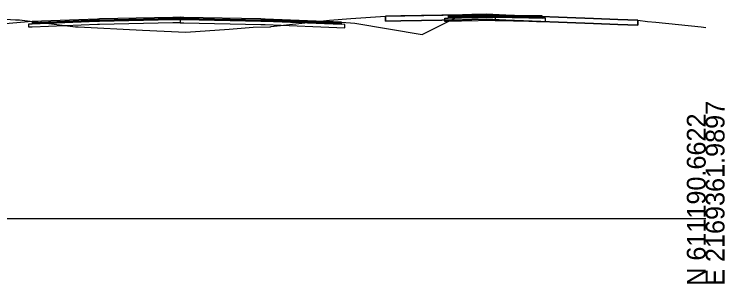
# Model space of a CAD drawing. Extents: x -26 to 1303, y -3010 to 12038.
# Drawn here: x 1197.1 to 1302.8, y 5990.3 to 6030.4 of the extents above; entities that cross this region are included whole.
import ezdxf

# ---------------------------------------------------------------- set-up
doc = ezdxf.new("R2010")
doc.units = 0
for name, color, linetype in [('RD_GPK_XS_Cell', 7, 'Continuous'), ('RD_XS_Base', 7, 'Continuous'), ('RD_XS_ExGround', 7, 'Continuous'), ('RD_XS_ExPaveRet', 7, 'Continuous'), ('RD_XS_Greenside', 7, 'Continuous'), ('RD_XS_Pave', 7, 'Continuous'), ('RD_XS_PaveOvlay_CP', 7, 'Continuous'), ('RD_XS_TieSlope', 7, 'Continuous')]:
    doc.layers.add(name, color=color, linetype=linetype)

msp = doc.modelspace()

# ---------------------------------------------------------------- linework, layer by layer
at = {"layer": 'RD_GPK_XS_Cell'}
msp.add_line((1150, 6000), (1300, 6000), dxfattribs=at)
at = {"layer": 'RD_XS_Base'}
for p, q in [((1209.82, 6029.34), (1220.74, 6029.56)), ((1220.74, 6029.56), (1221.82, 6029.58)), ((1221.82, 6029.73), (1221.82, 6029.74)), ((1221.82, 6029.74), (1221.82, 6029.71)), ((1221.82, 6029.58), (1221.82, 6029.73)), ((1221.82, 6029.71), (1221.82, 6029.08)), ((1221.82, 6029.58), (1221.82, 6029.56)), ((1221.82, 6029.58), (1221.82, 6029.58)), ((1222.37, 6029.57), (1221.82, 6029.58)), ((1221.82, 6029.58), (1221.82, 6029.58)), ((1221.82, 6029.56), (1221.82, 6029.08)), ((1233.82, 6029.34), (1222.37, 6029.57)), ((1261.19, 6029.77), (1261.69, 6029.78)), ((1261.19, 6029.27), (1261.19, 6029.77)), ((1261.69, 6029.78), (1263.69, 6029.82)), ((1263.69, 6029.82), (1268.69, 6029.92)), ((1268.69, 6030), (1268.69, 6030.08)), ((1268.69, 6030.08), (1268.69, 6029.77)), ((1268.69, 6029.92), (1268.69, 6030)), ((1271.42, 6029.86), (1268.69, 6029.92)), ((1268.69, 6029.92), (1268.69, 6029.42)), ((1268.69, 6029.77), (1268.69, 6029.42)), ((1273.69, 6029.82), (1271.42, 6029.86)), ((1274.58, 6029.8), (1273.69, 6029.82)), ((1275.69, 6029.78), (1274.58, 6029.8)), ((1275.91, 6029.77), (1275.69, 6029.78)), ((1276.19, 6029.77), (1275.91, 6029.77)), ((1276.19, 6029.49), (1276.19, 6029.77)), ((1199.32, 6028.92), (1199.81, 6028.94)), ((1199.32, 6028.91), (1199.32, 6028.92)), ((1199.32, 6028.42), (1199.32, 6028.91)), ((1199.81, 6028.94), (1199.82, 6028.94)), ((1199.82, 6028.94), (1209.52, 6029.33)), ((1209.52, 6028.83), (1199.82, 6028.44)), ((1209.52, 6029.33), (1209.82, 6029.34)), ((1209.82, 6028.84), (1209.52, 6028.83)), ((1220.74, 6029.06), (1209.82, 6028.84)), ((1221.82, 6029.08), (1220.74, 6029.06)), ((1221.82, 6029.08), (1222.37, 6029.07)), ((1222.37, 6029.07), (1233.82, 6028.84)), ((1234.46, 6029.31), (1233.82, 6029.34)), ((1233.82, 6028.84), (1234.49, 6028.81)), ((1245.82, 6028.86), (1234.46, 6029.31)), ((1234.49, 6028.81), (1246.32, 6028.34)), ((1245.85, 6028.86), (1245.82, 6028.86)), ((1246.32, 6028.84), (1245.85, 6028.86)), ((1246.32, 6028.81), (1246.32, 6028.84)), ((1246.32, 6028.34), (1246.32, 6028.81)), ((1261.69, 6029.28), (1261.19, 6029.27)), ((1263.69, 6029.32), (1261.69, 6029.28)), ((1268.69, 6029.42), (1263.69, 6029.32)), ((1268.69, 6029.42), (1271.42, 6029.36)), ((1271.42, 6029.36), (1273.69, 6029.32)), ((1273.69, 6029.32), (1274.81, 6029.3)), ((1274.81, 6029.3), (1276.19, 6029.27)), ((1276.19, 6029.27), (1276.19, 6029.49)), ((1199.81, 6028.44), (1199.32, 6028.42)), ((1199.82, 6028.44), (1199.81, 6028.44))]:
    msp.add_line(p, q, dxfattribs=at)
at = {"layer": 'RD_XS_ExGround'}
msp.add_lwpolyline([(1188.24, 6030.14), (1197.33, 6029.54), (1197.85, 6029.51), (1197.9, 6029.51), (1206.26, 6028.51), (1206.35, 6028.5), (1206.37, 6028.5), (1206.41, 6028.5), (1206.64, 6028.49), (1216.21, 6027.99), (1222.67, 6027.71), (1229.12, 6028.16), (1232.7, 6028.45), (1235.17, 6028.51), (1235.24, 6028.51), (1235.37, 6028.52), (1244.05, 6029.5), (1247.21, 6029.71), (1252.38, 6030.08), (1263.8, 6030.29), (1267.33, 6030.36), (1283.32, 6029.71), (1289.91, 6029.46), (1291.34, 6029.3), (1292.57, 6029.18), (1299.32, 6028.5), (1300, 6028.4)], dxfattribs=at)
at = {"layer": 'RD_XS_ExPaveRet'}
for p, q in [((1254.65, 6030.12), (1252.38, 6030.08)), ((1263.8, 6030.29), (1254.65, 6030.12)), ((1265.21, 6030.32), (1263.8, 6030.29)), ((1267.33, 6030.36), (1265.21, 6030.32))]:
    msp.add_line(p, q, dxfattribs=at)
for points in [[(1289.91, 6029.46), (1289.91, 6029.46), (1289.91, 6029.22), (1289.91, 6028.71), (1289.91, 6028.71), (1289.91, 6028.71), (1286.95, 6028.82), (1283.32, 6028.96), (1270.27, 6029.49), (1267.33, 6029.61), (1265.21, 6029.57), (1263.8, 6029.54), (1254.65, 6029.37), (1252.38, 6029.33), (1252.38, 6029.51), (1252.38, 6030.08), (1254.65, 6030.12), (1263.8, 6030.29), (1265.21, 6030.32), (1267.33, 6030.36), (1270.27, 6030.24), (1283.32, 6029.71), (1286.95, 6029.57), (1289.91, 6029.46), (1289.91, 6029.46)], [(1252.38, 6030.08), (1252.38, 6029.51), (1252.38, 6029.33), (1254.65, 6029.37), (1263.8, 6029.54), (1265.21, 6029.57), (1267.33, 6029.61), (1270.27, 6029.49), (1283.32, 6028.96), (1286.95, 6028.82), (1289.91, 6028.71), (1289.91, 6028.71), (1289.91, 6028.71), (1289.91, 6029.22), (1289.91, 6029.46), (1289.91, 6029.46), (1289.91, 6029.46)], [(1283.32, 6029.71), (1270.27, 6030.24), (1267.33, 6030.36)], [(1289.91, 6029.46), (1286.95, 6029.57), (1283.32, 6029.71)]]:
    msp.add_lwpolyline(points, dxfattribs=at)
at = {"layer": 'RD_XS_Greenside'}
for p, q in [((1257.82, 6027.35), (1263.69, 6030.29)), ((1247.82, 6029.02), (1257.82, 6027.35))]:
    msp.add_line(p, q, dxfattribs=at)
at = {"layer": 'RD_XS_Pave'}
for p, q in [((1209.52, 6029.65), (1199.82, 6029.26)), ((1209.82, 6029.66), (1209.52, 6029.65)), ((1220.74, 6029.88), (1209.82, 6029.66)), ((1220.74, 6029.72), (1209.82, 6029.5)), ((1209.82, 6029.5), (1220.74, 6029.72)), ((1209.82, 6029.34), (1220.74, 6029.56)), ((1221.82, 6029.9), (1220.74, 6029.88)), ((1221.82, 6029.74), (1220.74, 6029.72)), ((1220.74, 6029.72), (1221.82, 6029.74)), ((1220.74, 6029.56), (1221.82, 6029.58)), ((1222.37, 6029.89), (1221.82, 6029.9)), ((1221.82, 6029.73), (1221.82, 6029.74)), ((1221.82, 6029.74), (1222.37, 6029.73)), ((1222.37, 6029.73), (1221.82, 6029.74)), ((1221.82, 6029.74), (1221.82, 6029.74)), ((1221.82, 6029.74), (1221.82, 6029.74)), ((1221.82, 6029.74), (1221.82, 6029.73)), ((1221.82, 6029.58), (1221.82, 6029.73)), ((1221.82, 6029.73), (1221.82, 6029.58)), ((1221.82, 6029.58), (1221.82, 6029.58)), ((1221.82, 6029.58), (1221.82, 6029.58)), ((1221.82, 6029.58), (1222.37, 6029.57)), ((1233.82, 6029.66), (1222.37, 6029.89)), ((1222.37, 6029.73), (1233.82, 6029.5)), ((1233.82, 6029.5), (1222.37, 6029.73)), ((1222.37, 6029.57), (1233.82, 6029.34)), ((1234.46, 6029.63), (1233.82, 6029.66)), ((1245.82, 6029.18), (1234.46, 6029.63)), ((1262.64, 6030.12), (1261.69, 6030.1)), ((1261.69, 6030.1), (1261.69, 6030.02)), ((1261.69, 6030.02), (1261.69, 6029.94)), ((1263.69, 6029.98), (1261.69, 6029.94)), ((1261.69, 6029.94), (1262.64, 6029.96)), ((1261.69, 6029.94), (1261.69, 6029.78)), ((1261.69, 6029.78), (1263.69, 6029.82)), ((1263.69, 6030.14), (1262.64, 6030.12)), ((1262.64, 6029.96), (1263.69, 6029.98)), ((1266.36, 6030.19), (1263.69, 6030.14)), ((1268.69, 6030.08), (1263.69, 6029.98)), ((1263.69, 6029.98), (1266.36, 6030.03)), ((1263.69, 6029.82), (1268.69, 6029.92)), ((1268.69, 6030.24), (1266.36, 6030.19)), ((1266.36, 6030.03), (1268.69, 6030.08)), ((1271.42, 6030.18), (1268.69, 6030.24)), ((1268.69, 6030.08), (1271.42, 6030.02)), ((1273.69, 6029.98), (1268.69, 6030.08)), ((1268.69, 6030.08), (1268.69, 6029.92)), ((1268.69, 6029.92), (1268.69, 6030.08)), ((1268.69, 6029.92), (1273.69, 6029.82)), ((1273.69, 6030.14), (1271.42, 6030.18)), ((1271.42, 6030.02), (1273.69, 6029.98)), ((1274.58, 6030.12), (1273.69, 6030.14)), ((1273.69, 6029.98), (1274.58, 6029.96)), ((1275.69, 6029.94), (1273.69, 6029.98)), ((1273.69, 6029.82), (1275.69, 6029.78)), ((1275.69, 6030.1), (1274.58, 6030.12)), ((1274.58, 6029.96), (1275.69, 6029.94)), ((1275.69, 6030.03), (1275.69, 6030.1)), ((1275.69, 6029.94), (1275.69, 6030.03)), ((1275.69, 6029.78), (1275.69, 6029.94)), ((1209.52, 6029.49), (1199.82, 6029.1)), ((1199.82, 6029.1), (1209.52, 6029.49)), ((1199.82, 6028.94), (1209.52, 6029.33)), ((1199.82, 6029.26), (1199.82, 6029.25)), ((1199.82, 6029.25), (1199.82, 6029.1)), ((1199.82, 6029.1), (1199.82, 6029.09)), ((1199.82, 6029.09), (1199.82, 6028.94)), ((1209.82, 6029.5), (1209.52, 6029.49)), ((1209.52, 6029.49), (1209.82, 6029.5)), ((1209.52, 6029.33), (1209.82, 6029.34)), ((1233.82, 6029.5), (1234.46, 6029.47)), ((1234.46, 6029.47), (1233.82, 6029.5)), ((1233.82, 6029.34), (1234.46, 6029.31)), ((1234.46, 6029.47), (1245.82, 6029.02)), ((1245.82, 6029.02), (1234.46, 6029.47)), ((1234.46, 6029.31), (1245.82, 6028.86)), ((1245.82, 6029.17), (1245.82, 6029.18)), ((1245.82, 6029.02), (1245.82, 6029.17)), ((1245.82, 6029.01), (1245.82, 6029.02)), ((1245.82, 6028.86), (1245.82, 6029.01))]:
    msp.add_line(p, q, dxfattribs=at)
at = {"layer": 'RD_XS_PaveOvlay_CP'}
for p, q in [((1209.52, 6029.65), (1199.82, 6029.26)), ((1209.82, 6029.66), (1209.52, 6029.65)), ((1220.74, 6029.88), (1209.82, 6029.66)), ((1221.82, 6029.9), (1220.74, 6029.88)), ((1222.37, 6029.89), (1221.82, 6029.9)), ((1233.82, 6029.66), (1222.37, 6029.89)), ((1234.46, 6029.63), (1233.82, 6029.66)), ((1245.82, 6029.18), (1234.46, 6029.63)), ((1261.69, 6030.1), (1263.69, 6030.14)), ((1263.69, 6030.14), (1268.69, 6030.24)), ((1268.69, 6030.24), (1273.69, 6030.14)), ((1273.69, 6030.14), (1275.69, 6030.1))]:
    msp.add_line(p, q, dxfattribs=at)
at = {"layer": 'RD_XS_TieSlope'}
for p, q in [((1199.82, 6029.26), (1193.82, 6028.78)), ((1245.82, 6029.18), (1247.82, 6029.02))]:
    msp.add_line(p, q, dxfattribs=at)

# ---------------------------------------------------------------- texts
at = {"layer": 'RD_GPK_XS_Cell'}
for s, p in [('E 2169361.9897', (1302.8, 5990)), ('N 611190.6622', (1300, 5990))]:
    msp.add_text(s, height=2.8, rotation=90, dxfattribs=at).set_placement(p)

doc.saveas('drawing.dxf')
